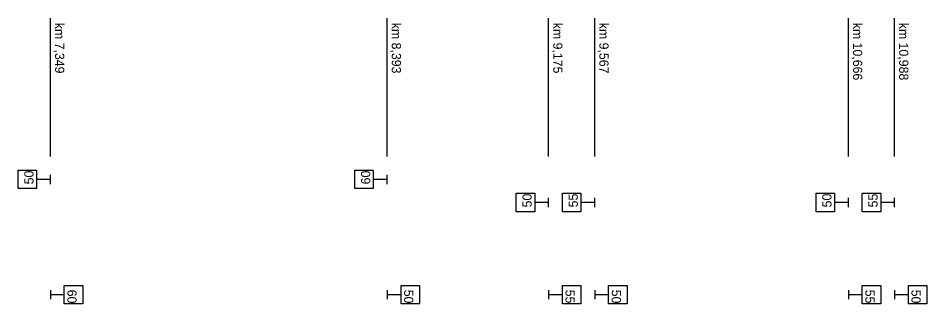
# Model space of a CAD drawing. Extents: x -591 to 5777, y 380 to 2087.
# Drawn here: x 2680 to 2877, y 1988 to 2050 of the extents above; entities that cross this region are included whole.
import ezdxf

# ---------------------------------------------------------------- set-up
doc = ezdxf.new("R2010")
doc.units = 0
doc.layers.add('rychlostník', color=7, linetype='Continuous')

msp = doc.modelspace()

# ---------------------------------------------------------------- linework, layer by layer
at = {"layer": 'rychlostník'}
for p, q in [((2687, 2020), (2687, 2050)), ((2760, 2020), (2760, 2050)), ((2795, 2020), (2795, 2050)), ((2795, 2020), (2795, 2050)), ((2805, 2020), (2805, 2050)), ((2805, 2020), (2805, 2050)), ((2860, 2020), (2860, 2050)), ((2860, 2020), (2860, 2050)), ((2870, 2020), (2870, 2050)), ((2870, 2020), (2870, 2050)), ((2680, 2013), (2680, 2017)), ((2680, 2017), (2684, 2017)), ((2684, 2017), (2684, 2013)), ((2687, 2014), (2687, 2016)), ((2753, 2013), (2753, 2017)), ((2753, 2017), (2757, 2017)), ((2757, 2017), (2757, 2013)), ((2760, 2014), (2760, 2016)), ((2687, 2015), (2684, 2015)), ((2760, 2015), (2757, 2015)), ((2684, 2013), (2680, 2013)), ((2757, 2013), (2753, 2013)), ((2788, 2008), (2788, 2012)), ((2788, 2012), (2792, 2012)), ((2792, 2012), (2792, 2008)), ((2798, 2008), (2798, 2012)), ((2798, 2012), (2802, 2012)), ((2802, 2012), (2802, 2008)), ((2853, 2008), (2853, 2012)), ((2853, 2012), (2857, 2012)), ((2857, 2012), (2857, 2008)), ((2863, 2008), (2863, 2012)), ((2863, 2012), (2867, 2012)), ((2867, 2012), (2867, 2008)), ((2790.33, 2010.09), (2790.33, 2010.09)), ((2795, 2010), (2792, 2010)), ((2795, 2009), (2795, 2011)), ((2800.33, 2010.09), (2800.33, 2010.09)), ((2805, 2010), (2802, 2010)), ((2805, 2009), (2805, 2011)), ((2855.33, 2010.09), (2855.33, 2010.09)), ((2860, 2010), (2857, 2010)), ((2860, 2009), (2860, 2011)), ((2865.33, 2010.09), (2865.33, 2010.09)), ((2870, 2010), (2867, 2010)), ((2870, 2009), (2870, 2011)), ((2792, 2008), (2788, 2008)), ((2802, 2008), (2798, 2008)), ((2857, 2008), (2853, 2008)), ((2867, 2008), (2863, 2008)), ((2690, 1992), (2694, 1992)), ((2690, 1988), (2690, 1992)), ((2694, 1992), (2694, 1988)), ((2763, 1992), (2767, 1992)), ((2763, 1988), (2763, 1992)), ((2767, 1992), (2767, 1988)), ((2798, 1992), (2802, 1992)), ((2798, 1988), (2798, 1992)), ((2802, 1992), (2802, 1988)), ((2808, 1992), (2812, 1992)), ((2808, 1988), (2808, 1992)), ((2812, 1992), (2812, 1988)), ((2863, 1992), (2867, 1992)), ((2863, 1988), (2863, 1992)), ((2867, 1992), (2867, 1988)), ((2873, 1992), (2877, 1992)), ((2873, 1988), (2873, 1992)), ((2877, 1992), (2877, 1988)), ((2687, 1991), (2687, 1989)), ((2687, 1990), (2690, 1990)), ((2760, 1991), (2760, 1989)), ((2760, 1990), (2763, 1990)), ((2795, 1991), (2795, 1989)), ((2795, 1990), (2798, 1990)), ((2799.67, 1989.91), (2799.67, 1989.91)), ((2805, 1991), (2805, 1989)), ((2805, 1990), (2808, 1990)), ((2809.67, 1989.91), (2809.67, 1989.91)), ((2860, 1991), (2860, 1989)), ((2860, 1990), (2863, 1990)), ((2864.67, 1989.91), (2864.67, 1989.91)), ((2870, 1991), (2870, 1989)), ((2870, 1990), (2873, 1990)), ((2874.67, 1989.91), (2874.67, 1989.91)), ((2694, 1988), (2690, 1988)), ((2767, 1988), (2763, 1988)), ((2802, 1988), (2798, 1988)), ((2812, 1988), (2808, 1988)), ((2867, 1988), (2863, 1988)), ((2877, 1988), (2873, 1988))]:
    msp.add_line(p, q, dxfattribs=at)

# ---------------------------------------------------------------- texts
for s, rotation, p in [('km 7,349', 270, (2688, 2049)), ('km 8,393', 270, (2761, 2049)), ('km 9,175', 270, (2796, 2049)), ('km 9,567', 270, (2806, 2049)), ('km 10,666', 270, (2861, 2049)), ('km 10,988', 270, (2871, 2049)), ('50', 90, (2683.33, 2013.93)), ('60', 90, (2756.33, 2013.93)), ('50', 90, (2791.33, 2008.93)), ('55', 90, (2801.33, 2008.93)), ('50', 90, (2856.33, 2008.93)), ('55', 90, (2866.33, 2008.93)), ('60', 270, (2690.67, 1991.07)), ('50', 270, (2763.67, 1991.07)), ('55', 270, (2798.67, 1991.07)), ('50', 270, (2808.67, 1991.07)), ('55', 270, (2863.67, 1991.07)), ('50', 270, (2873.67, 1991.07))]:
    msp.add_text(s, height=2, rotation=rotation, dxfattribs=at).set_placement(p)

doc.saveas('drawing.dxf')
